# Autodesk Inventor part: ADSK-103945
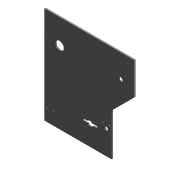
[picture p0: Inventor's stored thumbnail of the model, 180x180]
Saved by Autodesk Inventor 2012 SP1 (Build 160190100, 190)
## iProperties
Shininess: 0.0
Created: 2000-10
Part Number: ADSK-103945
Document SubType Name: Modeling
Designer: gao
Stock Number: ADSK-103945
Density: 1 g/cm^3
Material: Default
Density: 0.0
Volumn: 0.0
Area: 0.0
PropertySet Name: Model Information
Control State: 0
Master: False
Checked Out: False
Author: gao
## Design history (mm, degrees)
node "Extrusion1" dims "d2" = 28.575, "d3" = 0
  sketch "Sketch1"
    geometry: L1 (-24.403, 1801.054)-(1804.397, 1801.054); L2 (1804.397, 1801.054)-(1804.397, 1140.654); L3 (1347.197, -27.746)-(-24.403, -27.746); L4 (-24.403, -27.746)-(-24.403, 1801.054); L5 (1804.397, 1140.654)-(1347.197, 683.454); L6 (1347.197, 683.454)-(1347.197, -27.746)
    constraints: 12 end point, 3 parallel, 1 horizontal, 1 perpendicular
    dimensions: "d0" = 1828.8 distance of L3.end L1.start; "d22" = 1828.8 distance of L1.start L1.end; "d23" = 1371.6 distance of L3.start L3.end; "d24" = 711.2 distance of L5.end L3.start; "d25" = 45 deg angle of L6 L5
node "Hole1" dims "d6" = 177.8, "d7" = 9.525, "d8" = 6.35, "d9" = 60 deg, "d10" = 19.05, "d11" = 118 deg
  sketch "Sketch2"
    geometry: L1 (-24.403, -27.746)-(-24.403, 1801.054) reference; L2 (1804.397, -27.746)-(-24.403, -27.746) reference; 1 further point
    dimensions: "d4" = 304.8 distance from line of L1 point (280.397, 1293.054); "d5" = 1320.8 distance from line of point (280.397, 1293.054) L2
node "Hole2" dims "d16" = 85.725, "d17" = 9.525, "d18" = 6.35, "d19" = 60 deg, "d20" = 19.05, "d21" = 118 deg
  sketch "Sketch3"
    geometry: C1 r 88.9 at (280.397, 1293.054) reference; C2 r 1144.411 at (280.397, 1293.054); 1 further point
    constraints: 1 centre point, 1 coincident
    dimensions: "d43" = 1244.6 horizontal distance of point (1524.997, 1318.454) C1.centre; "d44" = 25.4 vertical distance of point (1524.997, 1318.454) C1.centre
node "Hole3" dims "d28" = 107.95, "d29" = 9.525, "d30" = 6.35, "d31" = 60 deg, "d32" = 19.05, "d33" = 118 deg
  sketch "Sketch5"
    geometry: C1 r 88.9 at (280.397, 1293.054) reference; 1 further point
    dimensions: "d26" = 622.3 horizontal distance of point (902.697, 226.254) C1.centre; "d27" = 1066.8 vertical distance of C1.centre point (902.697, 226.254)
node "Hole4" dims "d37" = 19.812, "d38" = 9.525, "d39" = 6.35, "d40" = 60 deg, "d41" = 19.05, "d42" = 118 deg
  sketch "Sketch6"
    geometry: C1 r 88.9 at (280.397, 1293.054) reference; 2 further points
    dimensions: "d34" = 469.9 vertical distance of point (1651.997, 1762.954) C1.centre; "d35" = 101.6 distance of point (1651.997, 1762.954) point (1651.997, 1661.354); "d36" = 1371.6 horizontal distance of C1.centre point (1651.997, 1762.954)
node "Extrusion2" dims "d47" = 28.575, "d48" = 0
  sketch "Sketch7"
    geometry: L1 (1347.197, -27.746)-(-24.403, -27.746) reference; L2 (1804.397, 1801.054)-(1804.397, 1140.654) reference; L3 (-24.403, -27.746)-(-24.403, -180.146); L4 (-24.403, -180.146)-(1347.197, -180.146); L5 (1347.197, -27.746)-(1347.197, -180.146)
    constraints: 6 end point, 2 perpendicular, 1 parallel
    dimensions: "d49" = 152.4 distance of L1.end L3.end
node "Extrusion3" dims "d56" = 25.4, "d57" = 0
  sketch "Sketch9"
    geometry: L1 (1029.639, 204.651)-(952.162, 204.655); L2 (853.23, 204.661)-(775.753, 204.665); L3 (1029.642, 255.451)-(948.091, 255.455); L4 (857.307, 255.46)-(775.756, 255.465); A1 r 53.975 centre (902.697, 226.254) between (952.162, 204.655) and (853.23, 204.661) reference; A2 r 25.4 centre (1029.64, 230.051) between (1029.639, 204.651) and (1029.642, 255.451); A3 r 25.4 centre (775.754, 230.065) between (775.756, 255.465) and (775.753, 204.665)
    constraints: 8 end point, 8 point on circle, 8 tangent, 2 centre point
    dimensions: "d52" = 50.8 diameter of A2; "d53" = 127 distance of A1.centre A2.centre; "d54" = 50.8 diameter of A3 (= d52); "d55" = 127 distance of A3.centre A1.centre (= d53)
node "Hole5" dims "d60" = 14, "d61" = 9.525, "d62" = 6.35, "d63" = 60 deg, "d64" = 19.05, "d65" = 118 deg, "d122" = 12.7
  sketch "Sketch10"
    geometry: A1 r 53.975 centre (902.697, 226.254) between (853.23, 204.661) and (952.162, 204.655) reference; 1 further point
    dimensions: "d58" = 76.2 horizontal distance of point (978.897, 302.454) A1.centre; "d59" = 76.2 horizontal distance of point (978.897, 302.454) A1.centre
node "Circular Pattern1" dims "d66" = 40, "d68" = 90 deg
node "Hole6" dims "d75" = 26.924, "d76" = 9.525, "d77" = 6.35, "d78" = 60 deg, "d79" = 19.05, "d80" = 118 deg
  sketch "Sketch11"
    geometry: L1 (-24.403, -180.146)-(-24.403, 1801.054) reference; L2 (-24.403, -180.146)-(1347.197, -180.146) reference; L3 (1347.197, -180.146)-(1347.197, 683.454) reference; 4 further points
    dimensions: "d69" = 50.8 distance from line of point (26.397, 73.854) L1; "d70" = 127 distance of point (153.397, 73.854) point (26.397, 73.854); "d71" = 254 distance from line of point (26.397, 73.854) L2; "d72" = 50.8 distance from line of L3 point (1296.397, 391.354); "d73" = 127 distance of point (1169.397, 391.354) point (1296.397, 391.354); "d74" = 571.5 distance from line of L2 point (1296.397, 391.354)
node "Hole7" dims "d83" = 15.875, "d84" = 9.525, "d85" = 6.35, "d86" = 60 deg, "d87" = 19.05, "d88" = 118 deg
  sketch "Sketch12"
    geometry: C1 r 42.862 at (1524.997, 1318.454) reference; 1 further point
    dimensions: "d81" = 139.7 horizontal distance of point (1385.297, 1064.454) C1.centre; "d82" = 254 vertical distance of C1.centre point (1385.297, 1064.454)
node "Hole8" dims "d90" = 13.3858, "d91" = 9.525, "d92" = 6.35, "d93" = 60 deg, "d94" = 19.05, "d95" = 118 deg, "d123" = 12.7
  sketch "Sketch14"
    geometry: L1 (750.297, 327.854)-(750.297, 277.054); L2 (750.297, 175.454)-(750.297, 124.654); L3 (826.497, 302.454)-(733.791, 302.454); L4 (826.497, 150.054)-(733.791, 150.054); C1 r 7 at (826.497, 150.054) reference; C2 r 7 at (826.497, 302.454) reference; A1 r 8.636 centre (750.297, 277.054) between (741.661, 277.054) and (758.933, 277.054) reference; A2 r 8.636 centre (750.297, 327.854) between (758.933, 327.854) and (741.661, 327.854) reference; 2 further points
    constraints: 8 end point, 2 equal length, 2 midpoint, 2 point on line, 1 perpendicular
node "Extrusion4" dims "d99" = 25.4, "d100" = 0
  sketch "Sketch15"
    geometry: L1 (-24.403, -180.146)-(1347.197, -180.146) reference; L2 (1347.197, -180.146)-(1347.197, 683.454) reference; C1 r 38.1 at (1232.897, 302.454)
    constraints: 1 centre point
    dimensions: "d96" = 76.2 diameter of C1; "d97" = 114.3 distance from line of L2 C1.centre; "d98" = 482.6 distance from line of L1 C1.centre
node "Hole9" dims "d103" = 7.7978, "d104" = 9.525, "d105" = 6.35, "d106" = 60 deg, "d107" = 19.05, "d108" = 118 deg, "d124" = 12.7
  sketch "Sketch16" dims "d101" = 104.775
    geometry: L1 (1804.397, 1801.054)-(1804.397, 1140.654) reference; L2 (1524.997, 1318.454)-(1562.041, 1355.498); C1 r 42.862 at (1524.997, 1318.454) reference; 1 further point
    constraints: 2 end point, 1 coincident, 3 other
    dimensions: "d102" = 45 deg angle of L1 L2
node "Circular Pattern2" dims "d109" = 40, "d111" = 90 deg
node "Hole10" dims "d113" = 13.3858, "d114" = 9.525, "d115" = 6.35, "d116" = 60 deg, "d117" = 19.05, "d118" = 118 deg, "d125" = 12.7
  sketch "Sketch17" dims "d112" = 203.2
    geometry: L1 (1804.397, 1140.654)-(1347.197, 683.454) reference; L2 (280.397, 1293.054)-(352.239, 1364.896); C1 r 88.9 at (280.397, 1293.054) reference; 1 further point
    constraints: 2 end point, 1 coincident, 1 parallel, 3 other
node "Circular Pattern3" dims "d119" = 40, "d121" = 90 deg
sketch "Sketch23"
  geometry: L1 (24.403, 1801.054)-(24.403, -180.146) reference; L2 (125.754, 1184.355)-(-457.972, 1674.159) reference; L3 (-349.059, 1591.059)-(24.403, 1277.687); L4 (-280.397, 1293.054)-(-14.243, 1310.115); L5 (-280.397, 1293.054)-(-41.37, 1174.753); C1 r 88.9 at (-280.397, 1293.054) reference; C2 r 203.2 at (-280.397, 1293.054); A1 r 266.7 centre (-280.397, 1293.054) between (-14.243, 1310.115) and (-41.37, 1174.753); 2 further points
  constraints: 6 end point, 3 point on line, 2 centre point, 2 coincident, 2 point on circle, 1 parallel, 3 other
  dimensions: "d135" = 6.35 distance between parallel lines of L3 L2; "d136" = 406.4 diameter of C2; "d137" = 31.75 dimension on C2; "d138" = 31.75 dimension on A1 (= d137); "d139" = 30 deg angle of L4 L5
hole "Hole12" sketch "Sketch23" at (-14.243, 1310.115), (-69.826, 1188.836) diameter "d140" = 12.7; stored, may be unused: countersink angle "d144" = 60 deg, drill point angle "d146" = 118 deg; dims "d141" = 12.7, "d142" = 9.525, "d143" = 6.35, "d145" = 19.05
body "Solid1"
